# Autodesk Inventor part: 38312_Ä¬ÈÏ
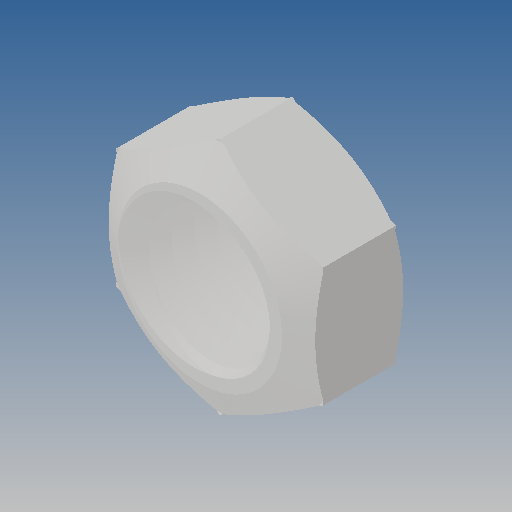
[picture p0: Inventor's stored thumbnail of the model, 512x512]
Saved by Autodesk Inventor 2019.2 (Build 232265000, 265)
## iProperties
Created: 2010-06
Part Number: 38312_Ä¬ÈÏ
Material: Ogólny
Document SubType Name: Modeling
Designer: CADENGINEERING4
Density: 1 g/cm^3
Appearance: Domyślna
Author: CADENGINEERING4
Revision Number: ÈÎºÎ
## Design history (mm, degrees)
feature "NONE"
node "Bryła1"
